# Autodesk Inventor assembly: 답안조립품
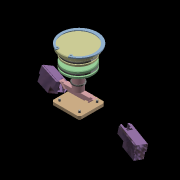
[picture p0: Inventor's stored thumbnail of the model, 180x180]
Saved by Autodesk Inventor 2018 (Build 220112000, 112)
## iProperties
Created: 2023-05
Part Number: 답안조립품
Material: 일반
Document SubType Name: Assembly
Designer: home
Author: home
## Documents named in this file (12)
- C:\Users\kimgi\Desktop\730506V1015\답안조립품.iam
- C:\Users\kimgi\Desktop\730506V1015\본체.ipt
- C:\Users\kimgi\Desktop\730506V1015\C형 구멍용 멈춤링 60x2.ipt
- C:\Users\kimgi\Desktop\730506V1015\O링 P16.ipt
- C:\Users\kimgi\Desktop\730506V1015\O링 P44.ipt
- C:\Users\kimgi\Desktop\730506V1015\볼트 M3 x 6.ipt
- C:\Users\kimgi\Desktop\730506V1015\볼트 M6 x 12.ipt
- C:\Users\kimgi\Desktop\730506V1015\앤드캡.ipt
- C:\Users\kimgi\Desktop\730506V1015\척.ipt
- C:\Users\kimgi\Desktop\730506V1015\커버.ipt
- C:\Users\kimgi\Desktop\730506V1015\피스톤 로드.ipt
- C:\Users\kimgi\Desktop\730506V1015\피스톤.ipt
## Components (7 placed, 5 different names)
1. C형 구멍용 멈춤링 60x2:1
2. O링 P16:1
3. O링 P44:1
4. 피스톤 로드:1 — 각도:1
5. 피스톤:1
6. O링 P44:2
7. O링 P16:2
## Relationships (1: Angle 1)
- 각도:1 [Angle]: 피스톤 로드:1
